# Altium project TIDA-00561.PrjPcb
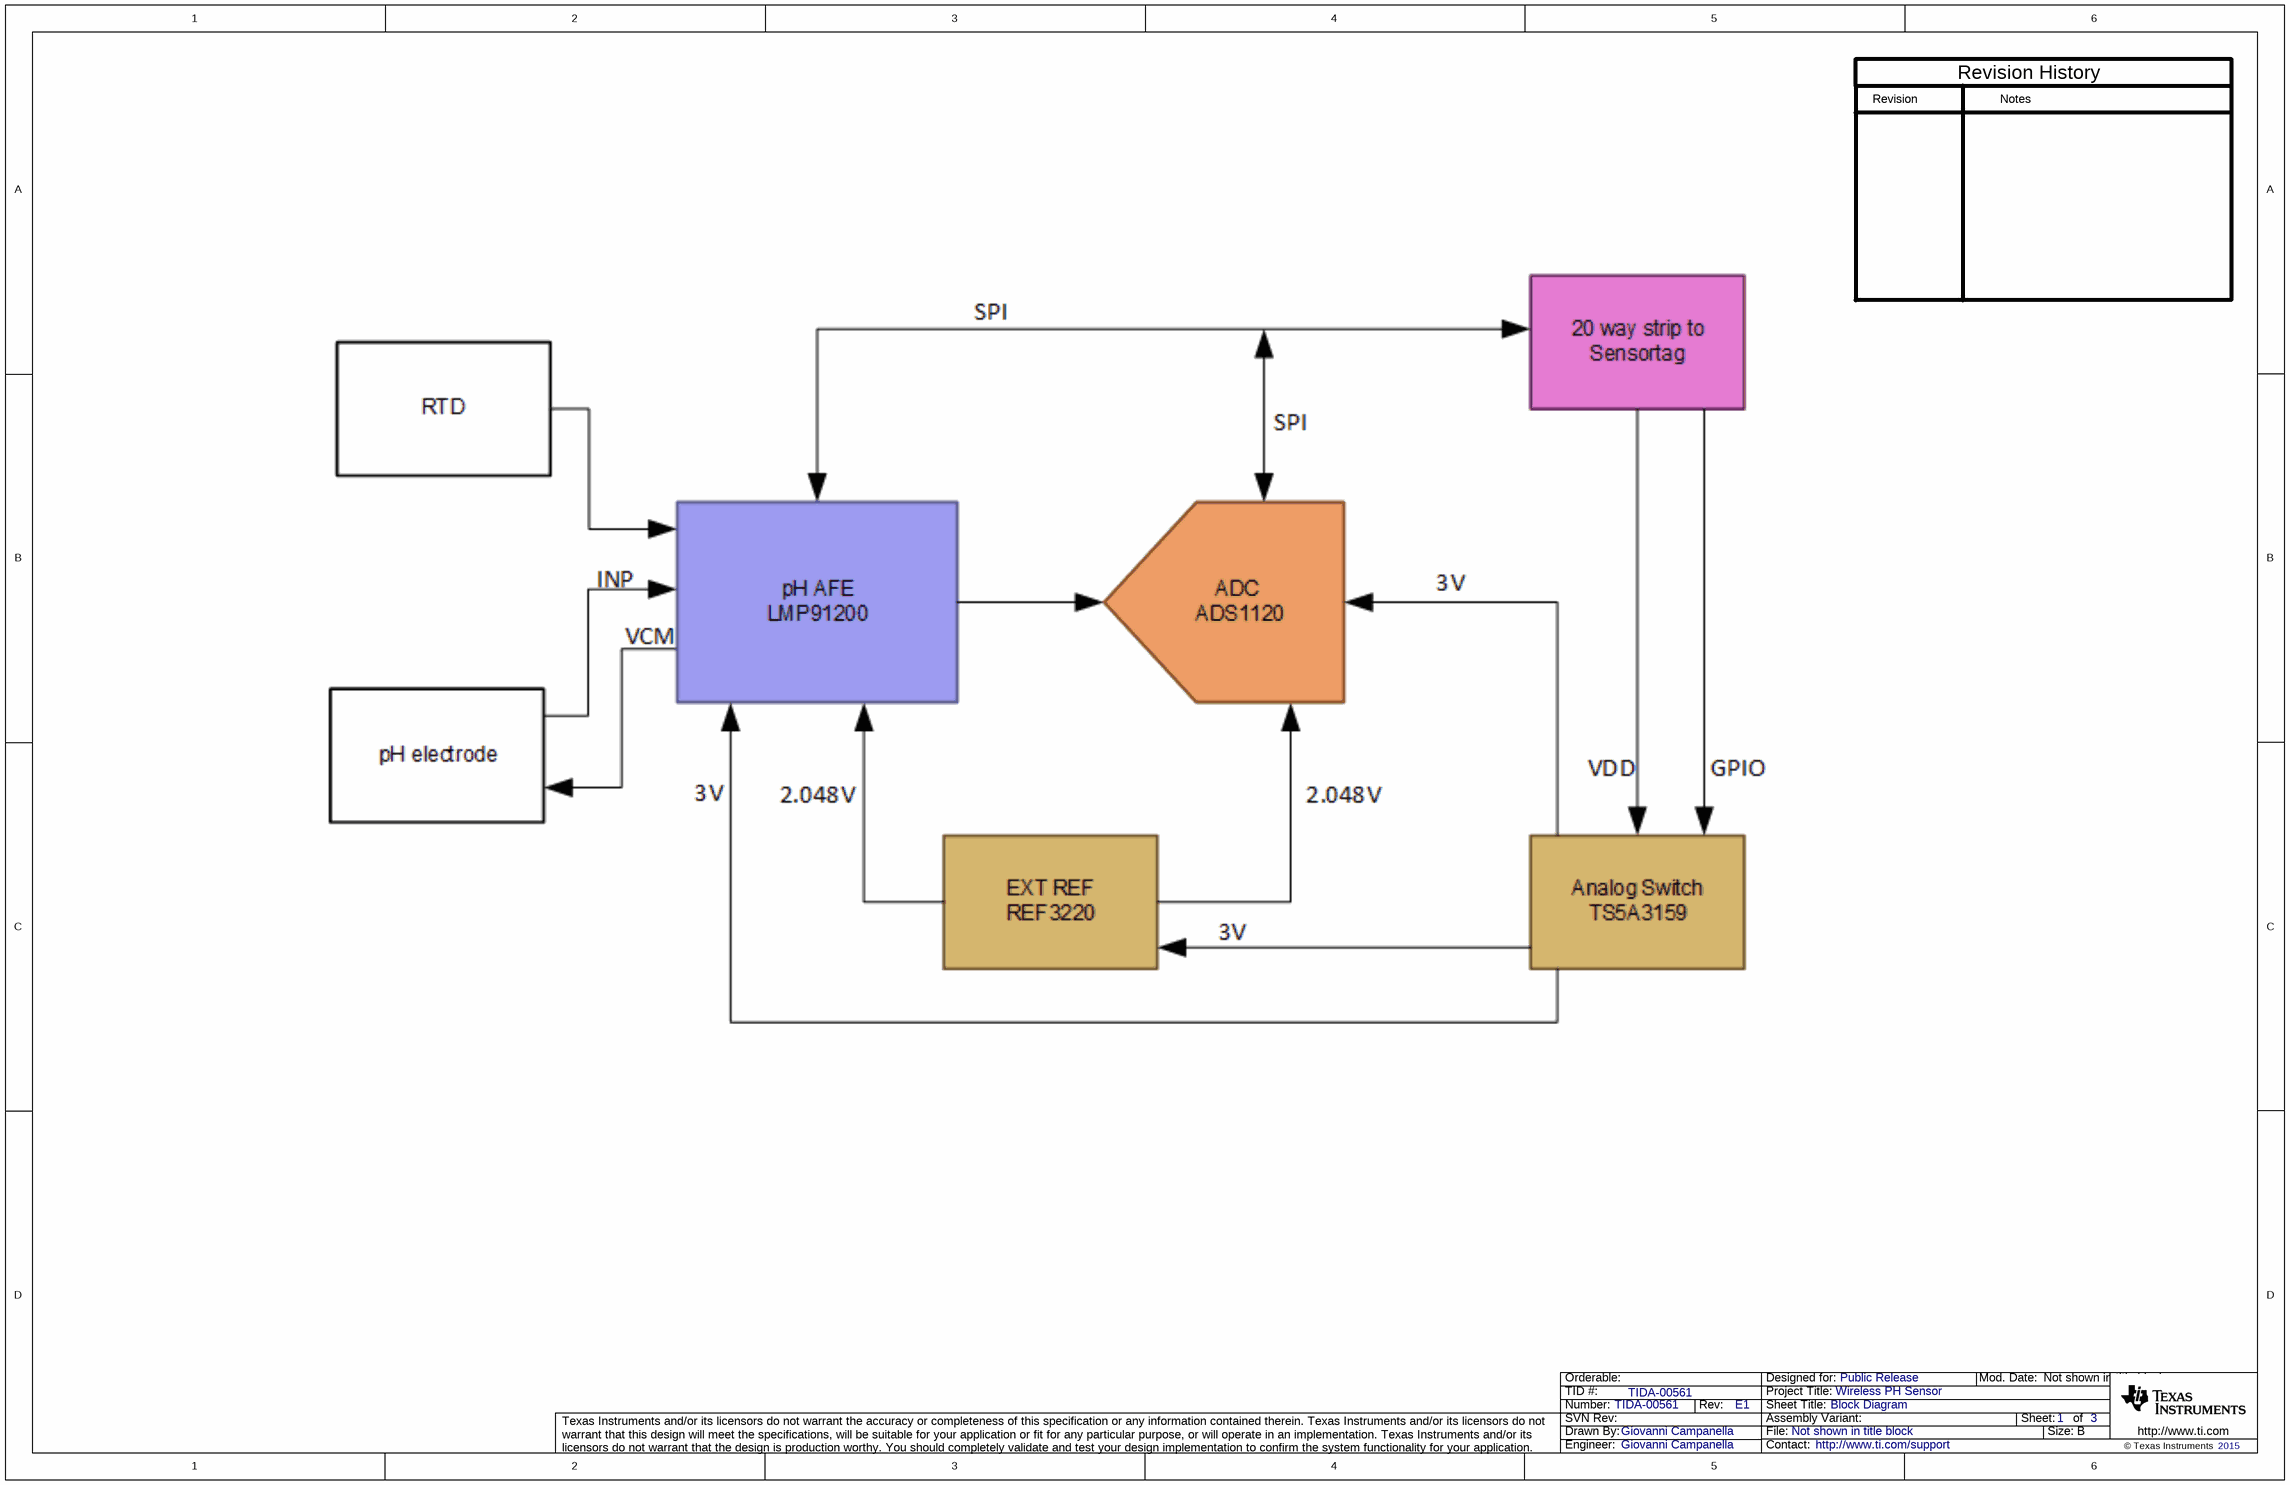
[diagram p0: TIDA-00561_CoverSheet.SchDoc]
CopyrightYear: 2015; PCB_Layout: Giovanni Campanella; PCB_Rev: E1; PRJ_Customer: Public Release; PRJ_Engineer: Giovanni Campanella; PRJ_Number: TIDA-00561; PRJ_Title: Wireless PH Sensor; SCH_Rev: E1; TechSupport: http://www.ti.com/support; TID: TIDA-00561
3 sheets, 41 parts. Net scope: global (net labels, ports and power ports of the same name join across sheets).
Board file: TIDA-00561.PcbDoc
Sheets:
  TIDA-00561_CoverSheet.SchDoc
  TIDA-00561_Wireless_pH.SchDoc
  TIDA-00561_Hardware.SchDoc

## Sheet TIDA-00561_CoverSheet.SchDoc: Block Diagram
size 431 x 279 mm; Date: Not shown in title block; ApprovedBy: Not shown in title block; CheckedBy: Not shown in title block; Author: Not shown in title block; CompanyName: Not shown in title block; DrawnBy: Giovanni Campanella; Engineer: Not shown in title block; Organization: Not shown in title block; Address1: Not shown in title block; Address2: Not shown in title block; Address3: Not shown in title block; Address4: Not shown in title block; DocumentNumber: 1; Revision: Use project parameter SCH_Rev; SheetNumber: 1; SheetTotal: 3; PageSetup: Record=PageOptions¦CenterHorizontal=True¦CenterVertical=True¦PrintScale=1.00¦XCorrection=1.00¦YCorrection=1.00¦PrintKind=0¦BorderSize=5000000¦LeftOffset=0¦BottomOffset=0¦Orientation=2¦PaperLength=1000¦PaperWidth=1000¦Scale=100¦PaperSource=15¦PrintQuality=600¦MediaType=1¦DitherType=10¦PaperKind=Letter¦PrintScaleMode=1

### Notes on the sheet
- Revision
- Notes
- Revision History

## Sheet TIDA-00561_Wireless_pH.SchDoc: Wireless PH Sensor
size 431 x 279 mm; Date: Not shown in title block; ApprovedBy: Not shown in title block; CheckedBy: Not shown in title block; Author: Not shown in title block; CompanyName: Texas Instruments; DrawnBy: Giovanni Campanella; Engineer: Giovanni Campanella; Organization: Not shown in title block; Address1: Not shown in title block; Address2: Not shown in title block; Address3: Not shown in title block; Address4: Not shown in title block; DocumentNumber: 2; Revision: Use project parameter SCH_Rev; SheetNumber: 2; SheetTotal: 3; PageSetup: Record=PageOptions¦CenterHorizontal=True¦CenterVertical=True¦PrintScale=0.61¦XCorrection=1.00¦YCorrection=1.00¦PrintKind=0¦BorderSize=5000000¦LeftOffset=0¦BottomOffset=0¦Orientation=2¦PaperLength=1000¦PaperWidth=1000¦Scale=100¦PaperSource=15¦PrintQuality=600¦MediaType=1¦DitherType=10¦PaperKind=Letter¦PrintScaleMode=1
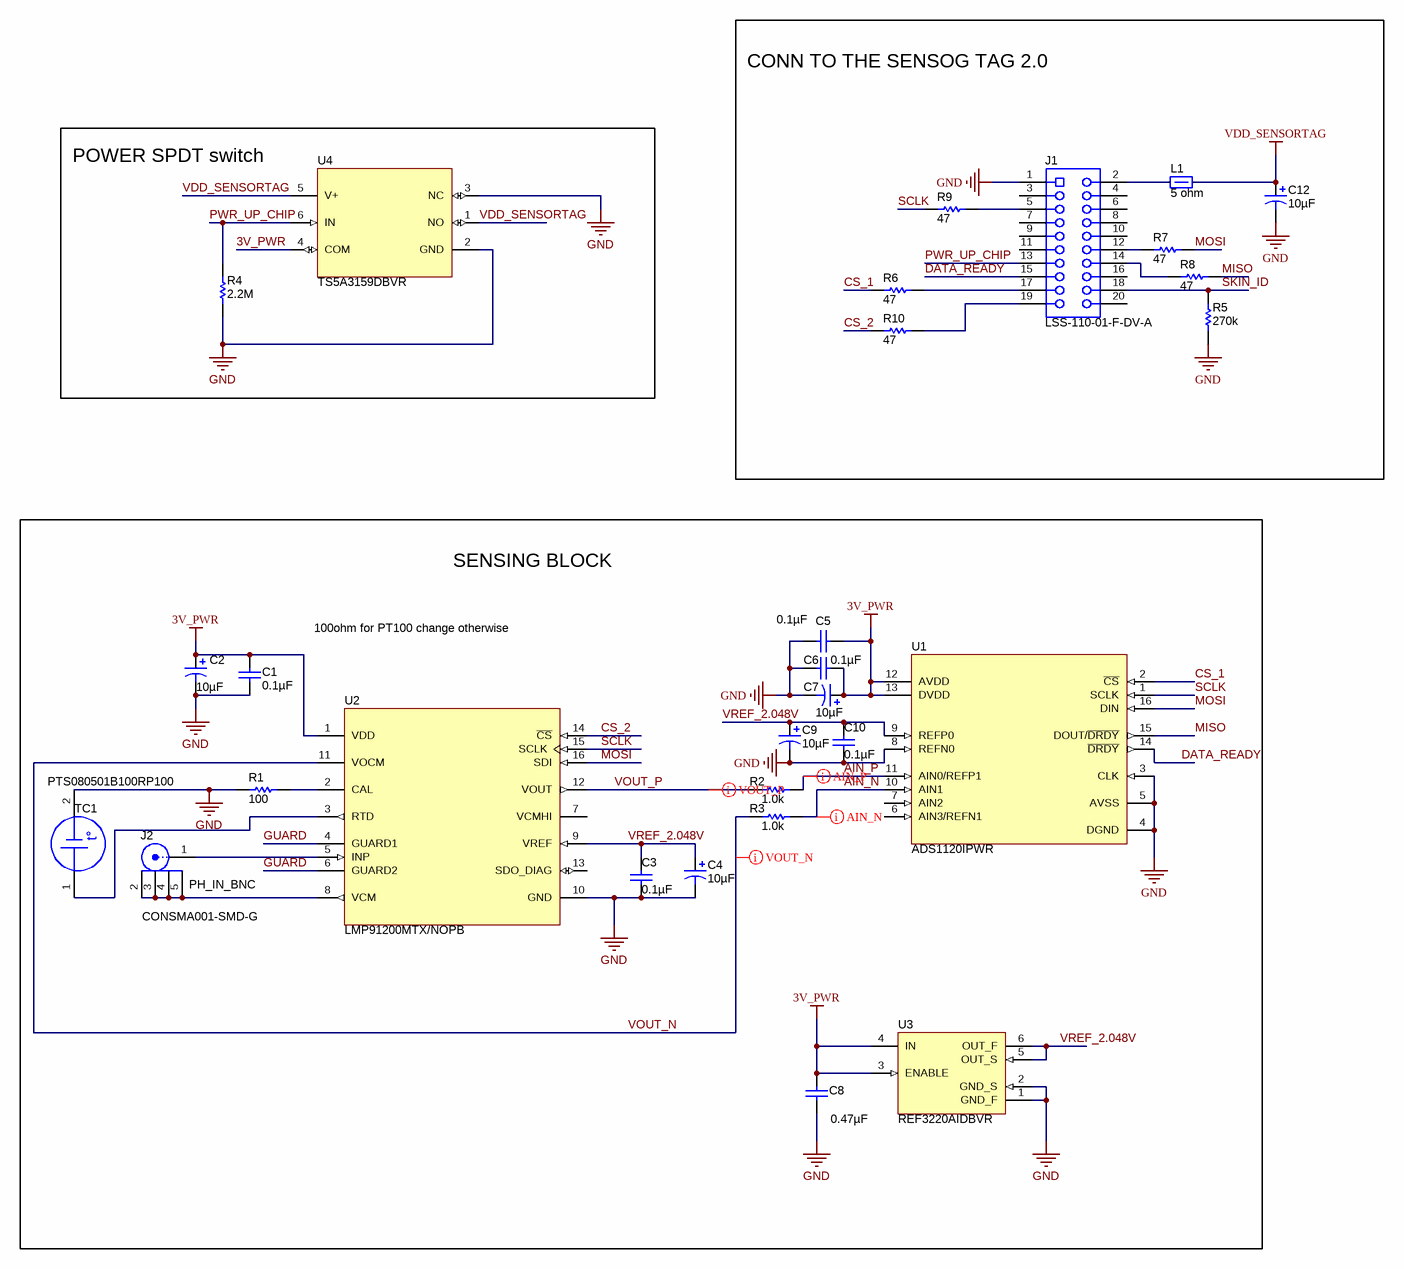
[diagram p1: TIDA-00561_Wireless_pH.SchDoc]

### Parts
C1  ValueDisplayed: 0.1µF  [0603]  (hidden comment: 06035C104KAT2A)
C2  ValueDisplayed: 10µF  [3216-18]  (hidden comment: 293D106X0010A2TE3)
C3  ValueDisplayed: 0.1µF  [0603]  (hidden comment: 06035C104KAT2A)
C4  ValueDisplayed: 10µF  [3216-18]  (hidden comment: 293D106X0010A2TE3)
C5  ValueDisplayed: 0.1µF  [0603]  (hidden comment: 06035C104KAT2A)
C6  ValueDisplayed: 0.1µF  [0603]  (hidden comment: 06035C104KAT2A)
C7  ValueDisplayed: 10µF  [3216-18]  (hidden comment: 293D106X0010A2TE3)
C8  ValueDisplayed: 0.47µF  [0603]  (hidden comment: GRM188R71C474KA88D)
C9  ValueDisplayed: 10µF  [3216-18]  (hidden comment: 293D106X0010A2TE3)
C10  ValueDisplayed: 0.1µF  [0603]  (hidden comment: 06035C104KAT2A)
C12  ValueDisplayed: 10µF  [3216-18]  (hidden comment: 293D106X0010A2TE3)
J1  LSS-110-01-F-DV-A  [Samtec_LSS-110-01-F-DV-A]
J2  CONSMA001-SMD-G  [Linx_CONSMA001-SMD-G]
L1  value 5 ohm  [0603]  (hidden comment: BLM18BB050SN1D)
R1  ValueDisplayed: 100  [0402]  (hidden comment: RG1005P-101-B-T5)
R2  ValueDisplayed: 1.0k  [0402]  (hidden comment: CRCW04021K00JNED)
R3  ValueDisplayed: 1.0k  [0402]  (hidden comment: CRCW04021K00JNED)
R4  ValueDisplayed: 2.2M  [0402]  (hidden comment: CRCW04022M20JNED)
R5  ValueDisplayed: 270k  [0402]  (hidden comment: CRCW0402270KJNED)
R6  ValueDisplayed: 47  [0402]  (hidden comment: CRCW040247R0JNED)
R7  ValueDisplayed: 47  [0402]  (hidden comment: CRCW040247R0JNED)
R8  ValueDisplayed: 47  [0402]  (hidden comment: CRCW040247R0JNED)
R9  ValueDisplayed: 47  [0402]  (hidden comment: CRCW040247R0JNED)
R10  ValueDisplayed: 47  [0402]  (hidden comment: CRCW040247R0JNED)
TC1  PTS080501B100RP100  [0805_HV]
U1  ADS1120IPWR  [PW0016A_N]
U2  LMP91200MTX/NOPB  [PW0016A_N]
U3  REF3220AIDBVR  [DBV0006A_N]
U4  TS5A3159DBVR  [DBV0006A_N]

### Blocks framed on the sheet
CONN TO THE SENSOG TAG 2.0: C12 J1 L1 R5-R10
POWER SPDT switch: R4 U4
SENSING BLOCK: C1-C10 J2 R1-R3 TC1 U1-U3

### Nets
3V_PWR: C1.1 C2.1(+) C5.1 C6.1 C7.1(+) C8.1 U1.12(AVDD) U1.13(DVDD) U2.1(VDD) U3.3(ENABLE) U3.4(IN) U4.4(COM)
GND: C1.2 C2.2(-) C3.2 C4.2(-) C5.2 C6.2 C7.2(-) C8.2 C9.2(-) C10.2 C12.2(-) J1.1 R1.1 R4.1 R5.1 TC1.2(-) U1.3(CLK) U1.4(DGND) U1.5(AVSS) U1.8(REFN0) U2.10(GND) U3.1(GND_F) U3.2(GND_S) U4.2(GND) U4.3(NC)
VDD_SENSORTAG: C12.1(+) L1.2 U4.1(NO) U4.5(V+)
AIN_N: R3.2 U1.10(AIN1)
AIN_P: R2.2 U1.11(AIN0/REFP1)
CS_1: R6.1 U1.2(~{CS})
CS_2: R10.1 U2.14(~{CS})
DATA_READY: J1.15 U1.14(~{DRDY})
GUARD: U2.4(GUARD1) U2.6(GUARD2)
MISO: R8.2 U1.15(DOUT/~{DRDY})
MOSI: R7.2 U1.16(DIN) U2.16(SDI)
PWR_UP_CHIP: J1.13 R4.2 U4.6(IN)
SCLK: R9.1 U1.1(SCLK) U2.15(SCLK)
SKIN_ID: J1.18 R5.2
VOUT_N: R3.1 U2.11(VOCM)
VOUT_P: R2.1 U2.12(VOUT)
VREF_2.048V: C3.1 C4.1(+) C9.1(+) C10.1 U1.9(REFP0) U2.9(VREF) U3.5(OUT_S) U3.6(OUT_F)
NetJ1_2: J1.2 L1.1
NetJ1_5: J1.5 R9.2
NetJ1_12: J1.12 R7.1
NetJ1_14: J1.14 R8.1
NetJ1_17: J1.17 R6.2
NetJ1_19: J1.19 R10.2
NetJ2_1: J2.1 U2.5(INP)
NetJ2_2: J2.2 J2.3 J2.4 J2.5 U2.8(VCM)
NetR1_2: R1.2 U2.2(CAL)
NetTC1_1: TC1.1(+) U2.3(RTD)

Not connected (* = marked no-connect by the designer): J1 3 4 6 7 8 9 10 11 16 20; U1 6(AIN3/REFN1) 7(AIN2); U2 7(VCMHI) 13(SDO_DIAG)

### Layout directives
differential pair: AIN_N, AIN_P, VOUT_N, VOUT_P

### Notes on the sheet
- 100ohm for PT100 change otherwise
- (near J2) PH_IN_BNC

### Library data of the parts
C1 C3 C5 C6 C10 = 06035C104KAT2A: CAP, CERM, 0.1 µF, 50 V, +/- 10%, X7R, 0603; Manufacturer: AVX; Polarized: N; CompType: Capacitor; Value: 0.1uF; U/M: EA; Cap_F: 0.0000001; Tolerance_%: 10; Value1: Unknown; VDC_V: 50; Value2: 50V; TaMin_C: -55; TaMax_C: 125
C2 C4 C7 C9 C12 = 293D106X0010A2TE3: CAP, TA, 10uF, 10V, +/-20%, 3.4 ohm, SMD; Manufacturer: Vishay-Sprague; Polarized: Y; CompType: Capacitor; U/M: EA; Cap_F: 0.00001; Tolerance_%: 20; Value1: 3.4 ohm; VDC_V: 10; ESR_Ohm: 3.4; IRMS_A: 0.15; TaMin_C: -55; TaMax_C: 125; Cap_Case: A
C8 = GRM188R71C474KA88D: CAP, CERM, 0.47 µF, 16 V, +/- 10%, X7R, 0603; Manufacturer: MuRata; Polarized: N; CompType: Capacitor; Value: 0.47uF; U/M: EA; Cap_F: 0.00000047; Tolerance_%: 10; Value1: Unknown; VDC_V: 16; Value2: 16V; TaMin_C: -55; TaMax_C: 125
J1 = LSS-110-01-F-DV-A: Terminal/Socket Combo, 25mil, 10x2, Gold, SMT; Manufacturer: Samtec; SymbolCreator: a0412235; CompType: Connector; U/M: EA
J2 = CONSMA001-SMD-G: Jack, SMA, PCB, Gold, SMT; Manufacturer: Linx Technologies; SymbolCreator: X0208326; U/M: EA
L1 = BLM18BB050SN1D: Ferrite Bead, 5 ohm @ 100 MHz, 0.7 A, 0603; Manufacturer: MuRata; Imax_A: 0.7; DCR_ohm: 0.05; Value1: 0.05 ohm; Value2: 0.7A; ZTyp@100MHz_Ohm: 5
R1 = RG1005P-101-B-T5: RES, 100, 0.1%, 0.063 W, 0402; Manufacturer: Susumu Co Ltd; CompType: Resistor; Value: 100; Value_Code: 100R; Tolerance_%: 0.1; Power_W: 0.063; Value2: 0.063W; TempCo: 25 ppm/C; EIA_Code: E192; U/M: EA
R2 R3 = CRCW04021K00JNED: RES, 1.0 k, 5%, 0.063 W, 0402; Manufacturer: Vishay-Dale; CompType: Resistor; Value: 1.0k; Res_ohm: 1000; Value_Code: 1k00; Tolerance_%: 5; Power_W: 0.063; Value2: 0.063W; VDC_V: 50; TempCo: 200 ppm/C; EIA_Code: E24; U/M: EA
R4 = CRCW04022M20JNED: RES, 2.2 M, 5%, 0.063 W, 0402; Manufacturer: Vishay-Dale; CompType: Resistor; Value: 2.2Meg; Res_ohm: 2200000; Value_Code: 2M20; Tolerance_%: 5; Power_W: 0.063; Value2: 0.063W; VDC_V: 50; TempCo: 200 ppm/C; EIA_Code: E24; U/M: EA
R5 = CRCW0402270KJNED: RES, 270 k, 5%, 0.063 W, 0402; Manufacturer: Vishay-Dale; CompType: Resistor; Value: 270k; Res_ohm: 270000; Tolerance_%: 5; Power_W: 0.063; Value2: 0.063W; VDC_V: 50; TempCo: 200 ppm/C; EIA_Code: E24; U/M: EA
R6-R10 = CRCW040247R0JNED: RES, 47, 5%, 0.063 W, 0402; Manufacturer: Vishay-Dale; CompType: Resistor; Value: 47; Value_Code: 47R0; Tolerance_%: 5; Power_W: 0.063; Value2: 0.063W; VDC_V: 50; TempCo: 200 ppm/C; EIA_Code: E24; U/M: EA
TC1 = PTS080501B100RP100: Temperature Sensor, 100ohm, 1%, TC=+3850ppm, 0805, SMT; Manufacturer: Vishay/Beyschlag; SymbolCreator: a0411947; CompType: Temp Sensor
U1 = ADS1120IPWR: Low-Power, Low-Noise, 16-Bit ADC for Small-Signal Sensors, PW0016A; Manufacturer: Texas Instruments; SymbolCreator: Altium; CompType: IC; U/M: EA
U2 = LMP91200MTX/NOPB: Configurable AFE for Low-Power Chemical Sensing Applications, PW0016A; Alternate PartNumber: LMP91200MT/NOPB; Manufacturer: Texas Instruments; SymbolCreator: Altium; CompType: IC; U/M: EA
U3 = REF3220AIDBVR: 2.048 V, 4 ppm / degC, 100 uA Series (Bandgap) Voltage Reference, -40 to 125 degC, 6-pin SOT-23 (DBV), Green (RoHS & no Sb/Br); Manufacturer: Texas Instruments; Alternate Manufacturer: None; Alternate PartNumber: Equivalent; Initial Accuracy @ 25/deg C(%): 0.2; Iout/Iz(Max)(mA): 10; Iq(Max)(uA): 120; Rating: Catalog; SubFamily: Series Voltage Reference; Temp Coeff(Max)(ppm/ degree C): 7; Temp Coeff(Typ)(ppm/ degree C): 4; VI(Max)(V): 5.5; VI(Min)(V): 2.098; VO(V): 2.048
U4 = TS5A3159DBVR: 1-Ω SPDT Analog Switch, DBV0006A; Alternate PartNumber: TS5A3159DBVT; Manufacturer: Texas Instruments; SymbolCreator: a0799628; CompType: IC; U/M: EA

## Sheet TIDA-00561_Hardware.SchDoc: Hardware
size 431 x 279 mm; Date: Not shown in title block; ApprovedBy: Not shown in title block; CheckedBy: Not shown in title block; Author: Not shown in title block; CompanyName: Not shown in title block; DrawnBy: Giovanni Campanella; Engineer: Not shown in title block; Organization: Not shown in title block; Address1: Not shown in title block; Address2: Not shown in title block; Address3: Not shown in title block; Address4: Not shown in title block; DocumentNumber: 3; Revision: Use project parameter SCH_Rev; SheetNumber: 3; SheetTotal: 3; PageSetup: Record=PageOptions¦CenterHorizontal=True¦CenterVertical=True¦PrintScale=1.00¦XCorrection=1.00¦YCorrection=1.00¦PrintKind=0¦BorderSize=5000000¦LeftOffset=0¦BottomOffset=0¦Orientation=2¦PaperLength=1000¦PaperWidth=1000¦Scale=100¦PaperSource=15¦PrintQuality=600¦MediaType=1¦DitherType=10¦PaperKind=Letter¦PrintScaleMode=1
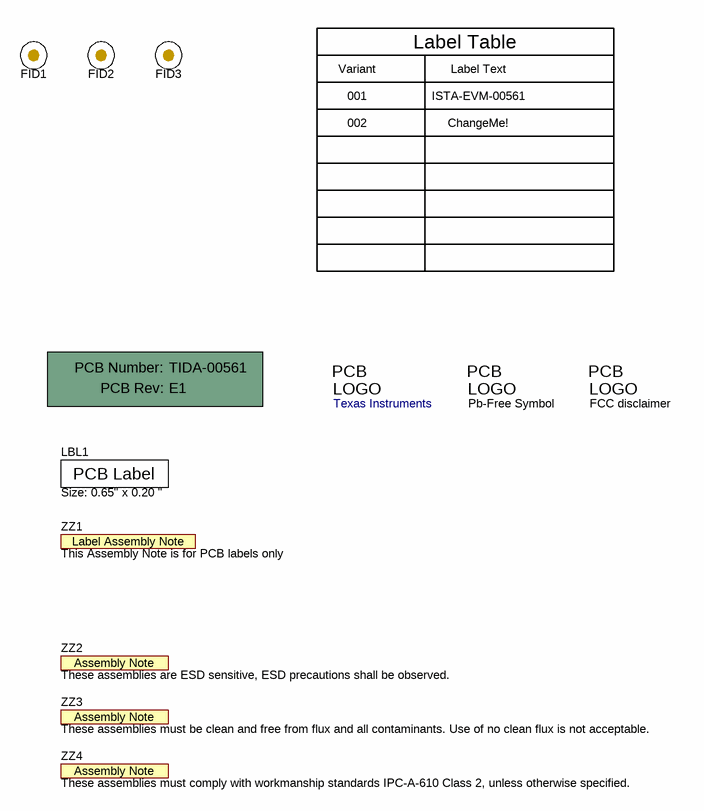
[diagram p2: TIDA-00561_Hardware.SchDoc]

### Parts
!PCB  Printed Circuit Board  (value not drawn)  (mechanical)
FID1  Fiducial  [Fiducial10-30]  (value not drawn)
FID2  Fiducial  [Fiducial10-30]  (value not drawn)
FID3  Fiducial  [Fiducial10-30]  (value not drawn)
LBL1  Size: 0.65" x 0.20 "  [Label_650x200]
Logo1  Texas Instruments  [TI_Symbol_Overlay_Small]  (no BOM)
Logo2  Pb-Free Symbol  [Pb-Free_Overlay_Small]  (no BOM)
Logo3  FCC disclaimer  [FCC_disclaimer]  (no BOM)
ZZ1  This Assembly Note is for PCB labels only  [AssemblyNoteLabel]  (no BOM)
ZZ2  These assemblies are ESD sensitive, ESD precautions shall be observed.  [AssemblyNote]  (no BOM)
ZZ3  These assemblies must be clean and free from flux and all contaminants. Use of no clean flux is not acceptable.  [AssemblyNote]  (no BOM)
ZZ4  These assemblies must comply with workmanship standards IPC-A-610 Class 2, unless otherwise specified.  [AssemblyNote]  (no BOM)

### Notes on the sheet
- Variant
- Label Table
- Label Text
- 001
- 002
- ISTA-EVM-00561
- ChangeMe!

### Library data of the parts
!PCB = PCB: Manufacturer: Any; PartNumber: TIDA-00561; SymbolCreator: a0412235
FID1-FID3 = Fiducial: Fiducial mark.  There is nothing to buy or mount.; SymbolCreator: codlsc
LBL1 = THT-14-423-10: Thermal Transfer Printable Labels, 0.650" W x 0.200" H - 10,000 per roll; Manufacturer: Brady; SymbolCreator: a0412235; CompType: Label
Logo1 = TI_Logo: Texas Instrument Corporate Signature; SymbolCreator: a0412235
Logo2 = Pb-Free: SymbolCreator: a0412235
Logo3 = FCC_disclaimer: SymbolCreator: codlsc
ZZ1 = AssemblyNoteLabel: SymbolCreator: a0412235
ZZ2-ZZ4 = AssemblyNote: SymbolCreator: codlsc

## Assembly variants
001: not fitted FID1 FID2 FID3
